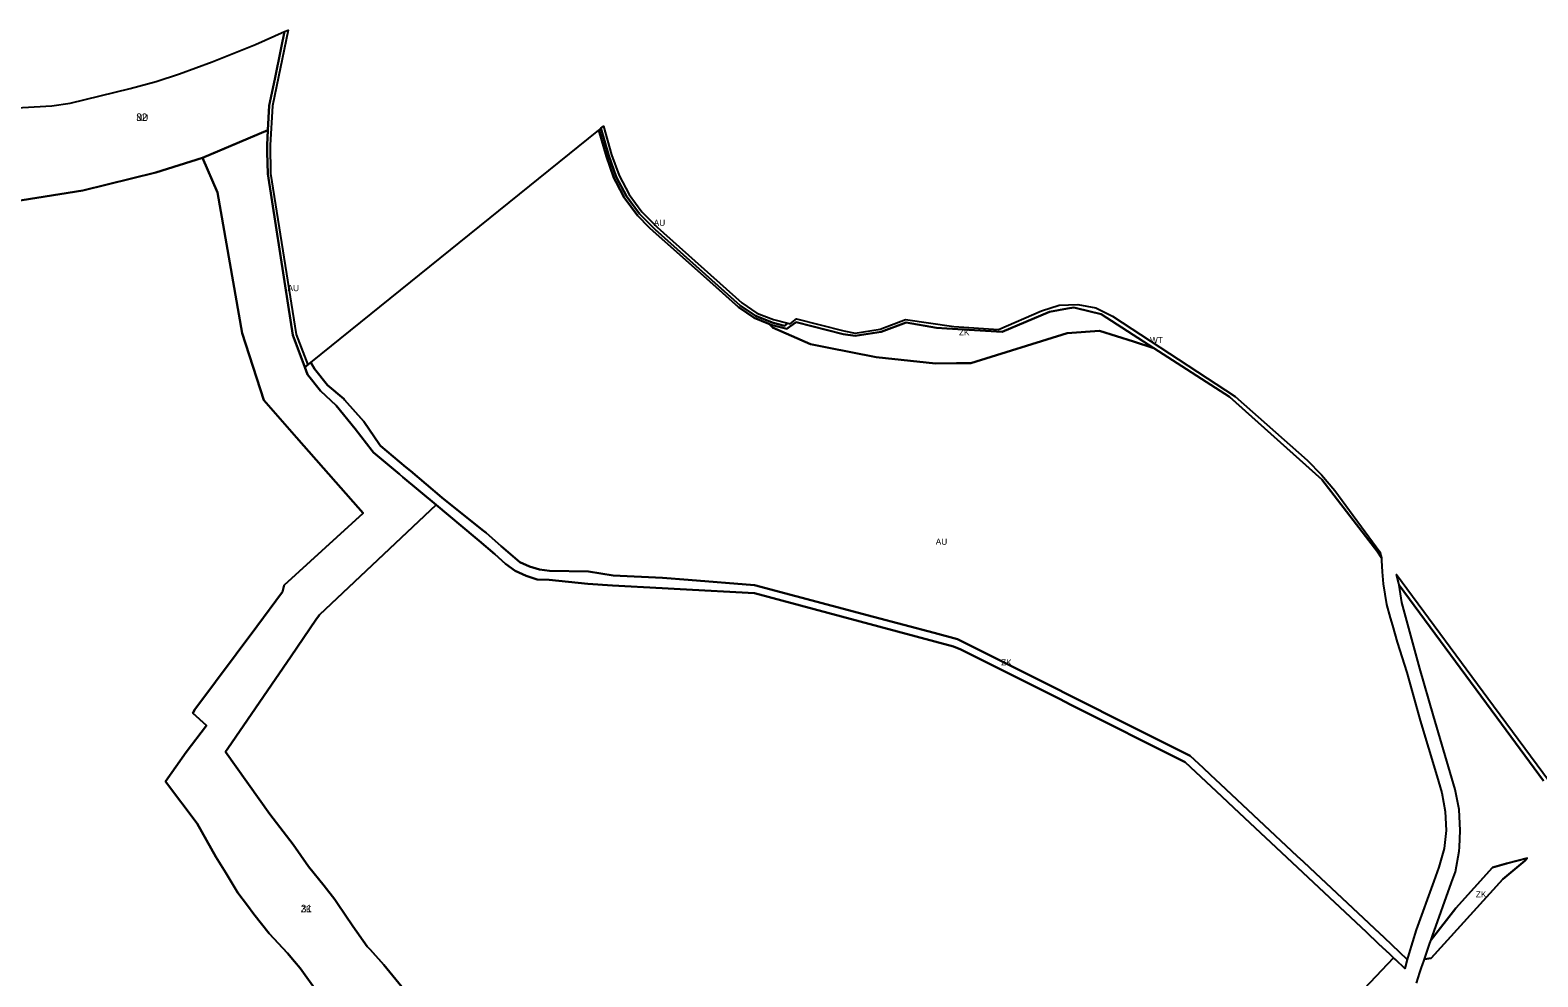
# Model space of a CAD drawing. Extents: x -541351 to -537540, y -1162694 to -1159725.
# Drawn here: x -539459 to -538243, y -1160701 to -1159939 of the extents above; entities that cross this region are included whole.
import ezdxf

# ---------------------------------------------------------------- set-up
doc = ezdxf.new("R2010")
doc.units = 0
for name, color, linetype in [('90640013', 7, 'Continuous'), ('90710013', 7, 'Continuous'), ('90710023', 7, 'Continuous'), ('90730023', 7, 'Continuous'), ('90750013', 7, 'Continuous'), ('ID_navrh', 7, 'Continuous')]:
    doc.layers.add(name, color=color, linetype=linetype)

msp = doc.modelspace()

# ---------------------------------------------------------------- linework, layer by layer
at = {"layer": '90640013'}
msp.add_lwpolyline([(-538370.49, -1160358.94), (-538369.3, -1160363.86), (-538372.22, -1160359.25), (-538417.44, -1160300.69), (-538491.9, -1160234.05), (-538552.96, -1160194.72), (-538595.44, -1160167.36), (-538615.23, -1160162.49), (-538617.34, -1160161.97), (-538622.38, -1160162.91), (-538637.02, -1160165.65), (-538675.11, -1160181.63), (-538719.64, -1160179.01), (-538728.21, -1160178.51), (-538752.52, -1160174.23), (-538772.82, -1160181.69), (-538793.6, -1160184.93), (-538803.32, -1160183.46), (-538841.31, -1160173.9), (-538846.77, -1160177.7), (-538848.8, -1160179.32), (-538860.75, -1160176.21), (-538863.2, -1160175.22), (-538875.02, -1160170.41), (-538887.73, -1160161.8), (-538910.96, -1160141.13), (-538935.46, -1160119.47), (-538956.49, -1160100.62), (-538959.62, -1160097.82), (-538969.1, -1160087.93), (-538979.86, -1160073.37), (-538986.39, -1160060.99), (-538988.26, -1160057.45), (-538994.28, -1160040.49), (-539000.5, -1160019.14), (-538998.75, -1160017.67), (-538992.36, -1160039.83), (-538986.31, -1160056.85), (-538978.16, -1160072.22), (-538967.47, -1160086.7), (-538955.06, -1160099.12), (-538886.36, -1160160.36), (-538874.16, -1160168.65), (-538859.9, -1160174.32), (-538850.66, -1160176.7), (-538848.02, -1160174.62), (-538846.13, -1160175.14), (-538840.94, -1160171.26), (-538822.03, -1160176.13), (-538802.78, -1160180.96), (-538793.68, -1160182.67), (-538773.4, -1160179.43), (-538753.21, -1160171.71), (-538714.09, -1160177.36), (-538678.11, -1160179.77), (-538643.45, -1160164.73), (-538629.14, -1160160.19), (-538614.23, -1160159.55), (-538599.49, -1160162.42), (-538586.2, -1160168.91), (-538487.18, -1160233.62), (-538429.21, -1160285.01), (-538417.52, -1160296.82), (-538407, -1160309.44)], close=True, dxfattribs=at)
msp.add_lwpolyline([(-538238.54, -1160543.48), (-538272.58, -1160497.42), (-538355.12, -1160385.74), (-538355.32, -1160384.48), (-538357.11, -1160377.08), (-538279, -1160482.96), (-538213.92, -1160570.92)], dxfattribs=at)
at = {"layer": '90710013'}
for points in [[(-538617.34, -1160161.97), (-538615.23, -1160162.49), (-538595.44, -1160167.36), (-538552.96, -1160194.72), (-538569.34, -1160189.52), (-538596.72, -1160180.83), (-538622.65, -1160182.66), (-538700.4, -1160206.89), (-538711.86, -1160206.99), (-538728.99, -1160207.15), (-538776.87, -1160201.94), (-538816.21, -1160194.19), (-538829.68, -1160191.54), (-538860.3, -1160178.14), (-538863.2, -1160175.22), (-538860.75, -1160176.21), (-538848.8, -1160179.32), (-538846.77, -1160177.7), (-538841.31, -1160173.9), (-538803.32, -1160183.46), (-538793.6, -1160184.93), (-538772.82, -1160181.69), (-538752.52, -1160174.23), (-538728.21, -1160178.51), (-538719.64, -1160179.01), (-538675.11, -1160181.63), (-538637.02, -1160165.65), (-538622.38, -1160162.91)], [(-539229.72, -1160211.49), (-539219.19, -1160224.51), (-539206.08, -1160235.73), (-539205.45, -1160236.44), (-539189.95, -1160253.97), (-539177.24, -1160272.53), (-539176.56, -1160273.52), (-539155.94, -1160290.64), (-539152.16, -1160293.52), (-539127.06, -1160315.25), (-539094.38, -1160341.15), (-539091.17, -1160343.7), (-539079.28, -1160354.4), (-539064.1, -1160367.35), (-539056.23, -1160370.78), (-539048.36, -1160373.06), (-539040.21, -1160374.33), (-539008.72, -1160374.73), (-538988.93, -1160377.95), (-538948.98, -1160379.96), (-538928.34, -1160381.56), (-538874.8, -1160385.7), (-538778.94, -1160411.23), (-538730.03, -1160424.25), (-538711.16, -1160429.21), (-538647.61, -1160461.1), (-538642.87, -1160463.48), (-538579.55, -1160495.26), (-538562.84, -1160503.65), (-538554.08, -1160508.04), (-538523.56, -1160523.26), (-538513.09, -1160533.06), (-538507.03, -1160538.72), (-538499.15, -1160546.09), (-538437.13, -1160604.1), (-538432.16, -1160608.74), (-538422.47, -1160617.85), (-538379.46, -1160658.24), (-538374.69, -1160662.73), (-538367.2, -1160669.76), (-538348.53, -1160687.31), (-538350.5, -1160694.55), (-538357.79, -1160687.71), (-538359.69, -1160685.93), (-538362.6, -1160683.19), (-538371.67, -1160674.68), (-538381.47, -1160665.47), (-538488.42, -1160565.07), (-538498.07, -1160556.01), (-538527.59, -1160528.3), (-538619.68, -1160482.15), (-538629.02, -1160477.47), (-538708.61, -1160437.58), (-538714.39, -1160435.25), (-538804.8, -1160411.03), (-538815.82, -1160408.08), (-538874.79, -1160392.29), (-538934.85, -1160388.95), (-538949.42, -1160388.13), (-538989.36, -1160385.91), (-539009.33, -1160384.8), (-539040.55, -1160381.4), (-539050.13, -1160381.07), (-539058.9, -1160378.15), (-539067.91, -1160374.21), (-539075.66, -1160368.49), (-539084.19, -1160360.78), (-539097, -1160350.07), (-539100.19, -1160347.41), (-539131.64, -1160321.1), (-539158.37, -1160298.74), (-539161.25, -1160296.33), (-539182.23, -1160278.79), (-539183.21, -1160277.53), (-539196.85, -1160259.88), (-539212.25, -1160241.09), (-539224.77, -1160229.29), (-539235.42, -1160215.92), (-539237.55, -1160210.2), (-539235.05, -1160208.26), (-539232.65, -1160206.32)], [(-538251.69, -1160605.72), (-538253.7, -1160607.81), (-538271.4, -1160622.7), (-538329.33, -1160686.32), (-538334.69, -1160687.17), (-538330.23, -1160674.25), (-538329.28, -1160671.49), (-538309.39, -1160646.13), (-538279.85, -1160613.21), (-538268.39, -1160610.16)]]:
    msp.add_lwpolyline(points, close=True, dxfattribs=at)
at = {"layer": '90710023'}
msp.add_lwpolyline([(-539226.94, -1160714.26), (-539241.32, -1160694.3), (-539245.9, -1160688.87), (-539251.45, -1160682.3), (-539266.3, -1160666.41), (-539278.49, -1160650.74), (-539283.75, -1160643.82), (-539291.4, -1160633.74), (-539301.24, -1160617.66), (-539309.15, -1160604.74), (-539324.22, -1160577.77), (-539349.79, -1160543.92), (-539333.25, -1160520.38), (-539316.91, -1160498.74), (-539327.896, -1160488.77), (-539326.21, -1160485.94), (-539276.18, -1160418.95), (-539255.5, -1160391.26), (-539254.28, -1160385.71), (-539190.466, -1160327.844), (-539212.408, -1160302.893), (-539244.187, -1160266.755), (-539270.58, -1160236.742), (-539288.051, -1160182.795), (-539307.802, -1160069.322), (-539320.05, -1160041.46), (-539307.802, -1160036.303), (-539267.32, -1160019.26), (-539267.84, -1160031.16), (-539267.74, -1160037), (-539267.44, -1160054.36), (-539250.94, -1160160.23), (-539247.17, -1160184.44), (-539237.55, -1160210.2), (-539235.42, -1160215.92), (-539224.77, -1160229.29), (-539212.25, -1160241.09), (-539196.85, -1160259.88), (-539183.21, -1160277.53), (-539182.23, -1160278.79), (-539161.25, -1160296.33), (-539158.37, -1160298.74), (-539131.64, -1160321.1), (-539225.75, -1160409.65), (-539228.529, -1160413.704), (-539248.605, -1160442.984), (-539299.619, -1160517.39), (-539301.519, -1160520.161), (-539265.58, -1160570.18), (-539246.94, -1160594.62), (-539234.4, -1160612.53), (-539221.81, -1160628.07), (-539213.34, -1160639.09), (-539211.27, -1160642.16), (-539198.78, -1160660.64), (-539187.18, -1160676.86), (-539184.91, -1160679.39), (-539173.73, -1160691.8), (-539159.22, -1160709.51)], dxfattribs=at)
at = {"layer": '90730023'}
msp.add_lwpolyline([(-539504.15, -1160057.74), (-539499.27, -1160048.44), (-539494.95, -1160040.2), (-539486.82, -1160024.7), (-539482.04, -1160015.57), (-539474.65, -1160001.49), (-539441.58, -1159999.6), (-539426.66, -1159997.49), (-539378.27, -1159985.56), (-539357.29, -1159979.97), (-539338.63, -1159973.85), (-539312.29, -1159964.05), (-539277.38, -1159950.13), (-539253.79, -1159939.77), (-539256.52, -1159952.89), (-539261.76, -1159978), (-539266.2, -1159999.29), (-539267.32, -1160019.26), (-539320.05, -1160041.46), (-539357.51, -1160053.36), (-539416.53, -1160067.73), (-539516.34, -1160083.61), (-539513.23, -1160077.01)], close=True, dxfattribs=at)
at = {"layer": '90750013'}
for points in [[(-539263.64, -1159999.6), (-539265.33, -1160031.19), (-539265.24, -1160054.12), (-539244.59, -1160183.77), (-539235.05, -1160208.26), (-539237.55, -1160210.2), (-539247.17, -1160184.44), (-539250.94, -1160160.23), (-539267.44, -1160054.36), (-539267.74, -1160037), (-539267.84, -1160031.16), (-539267.32, -1160019.26), (-539266.2, -1159999.29), (-539261.76, -1159978), (-539256.52, -1159952.89), (-539253.79, -1159939.77), (-539251.01, -1159938.59)], [(-538417.44, -1160300.69), (-538372.22, -1160359.25), (-538369.3, -1160363.86), (-538369.19, -1160365.99), (-538368.74, -1160375.12), (-538367.88, -1160384.77), (-538365.12, -1160401.34), (-538362.23, -1160412.05), (-538360.43, -1160418.26), (-538356.56, -1160431.65), (-538348.78, -1160456.25), (-538337.94, -1160494.81), (-538324.7, -1160539.29), (-538320.65, -1160553.21), (-538317.93, -1160568.07), (-538317.03, -1160583.49), (-538318.62, -1160597.9), (-538323.05, -1160612.86), (-538327.17, -1160624.4), (-538341.19, -1160663.56), (-538347.11, -1160682.71), (-538348.53, -1160687.31), (-538367.2, -1160669.76), (-538374.69, -1160662.73), (-538379.46, -1160658.24), (-538422.47, -1160617.85), (-538432.16, -1160608.74), (-538437.13, -1160604.1), (-538499.15, -1160546.09), (-538507.03, -1160538.72), (-538513.09, -1160533.06), (-538523.56, -1160523.26), (-538554.08, -1160508.04), (-538562.84, -1160503.65), (-538579.55, -1160495.26), (-538642.87, -1160463.48), (-538647.61, -1160461.1), (-538711.16, -1160429.21), (-538730.03, -1160424.25), (-538778.94, -1160411.23), (-538874.8, -1160385.7), (-538928.34, -1160381.56), (-538948.98, -1160379.96), (-538988.93, -1160377.95), (-539008.72, -1160374.73), (-539040.21, -1160374.33), (-539048.36, -1160373.06), (-539056.23, -1160370.78), (-539064.1, -1160367.35), (-539079.28, -1160354.4), (-539091.17, -1160343.7), (-539094.38, -1160341.15), (-539127.06, -1160315.25), (-539152.16, -1160293.52), (-539155.94, -1160290.64), (-539176.56, -1160273.52), (-539177.24, -1160272.53), (-539189.95, -1160253.97), (-539205.45, -1160236.44), (-539206.08, -1160235.73), (-539219.19, -1160224.51), (-539229.72, -1160211.49), (-539232.65, -1160206.32), (-539000.5, -1160019.14), (-538994.28, -1160040.49), (-538988.26, -1160057.45), (-538986.39, -1160060.99), (-538979.86, -1160073.37), (-538969.1, -1160087.93), (-538959.62, -1160097.82), (-538956.49, -1160100.62), (-538935.46, -1160119.47), (-538910.96, -1160141.13), (-538887.73, -1160161.8), (-538875.02, -1160170.41), (-538863.2, -1160175.22), (-538860.3, -1160178.14), (-538829.68, -1160191.54), (-538816.21, -1160194.19), (-538776.87, -1160201.94), (-538728.99, -1160207.15), (-538711.86, -1160206.99), (-538700.4, -1160206.89), (-538622.65, -1160182.66), (-538596.72, -1160180.83), (-538569.34, -1160189.52), (-538552.96, -1160194.72), (-538491.9, -1160234.05)], [(-538990.06, -1160039.15), (-538984.11, -1160055.68), (-538975.92, -1160070.9), (-538965.59, -1160084.97), (-538953.46, -1160097.34), (-538885.01, -1160158.23), (-538872.92, -1160166.48), (-538859.62, -1160171.76), (-538848.02, -1160174.62), (-538850.66, -1160176.7), (-538859.9, -1160174.32), (-538874.16, -1160168.65), (-538886.36, -1160160.36), (-538955.06, -1160099.12), (-538967.47, -1160086.7), (-538978.16, -1160072.22), (-538986.31, -1160056.85), (-538992.36, -1160039.83), (-538998.75, -1160017.67), (-538996.64, -1160015.93)]]:
    msp.add_lwpolyline(points, close=True, dxfattribs=at)
for points in [[(-539516.34, -1160083.61), (-539416.53, -1160067.73), (-539357.51, -1160053.36), (-539320.05, -1160041.46), (-539307.802, -1160069.322), (-539288.051, -1160182.795), (-539270.58, -1160236.742), (-539244.187, -1160266.755), (-539212.408, -1160302.893), (-539190.466, -1160327.844), (-539254.28, -1160385.71), (-539255.5, -1160391.26), (-539276.18, -1160418.95), (-539326.21, -1160485.94), (-539327.896, -1160488.77), (-539316.91, -1160498.74), (-539333.25, -1160520.38), (-539349.79, -1160543.92), (-539324.22, -1160577.77), (-539309.15, -1160604.74), (-539301.24, -1160617.66), (-539291.4, -1160633.74), (-539283.75, -1160643.82), (-539278.49, -1160650.74), (-539266.3, -1160666.41), (-539251.45, -1160682.3), (-539245.9, -1160688.87), (-539241.32, -1160694.3), (-539226.94, -1160714.26)], [(-539159.22, -1160709.51), (-539173.73, -1160691.8), (-539184.91, -1160679.39), (-539187.18, -1160676.86), (-539198.78, -1160660.64), (-539211.27, -1160642.16), (-539213.34, -1160639.09), (-539221.81, -1160628.07), (-539234.4, -1160612.53), (-539246.94, -1160594.62), (-539265.58, -1160570.18), (-539301.519, -1160520.161), (-539299.619, -1160517.39), (-539248.605, -1160442.984), (-539228.529, -1160413.704), (-539225.75, -1160409.65), (-539131.64, -1160321.1), (-539100.19, -1160347.41), (-539097, -1160350.07), (-539084.19, -1160360.78), (-539075.66, -1160368.49), (-539067.91, -1160374.21), (-539058.9, -1160378.15), (-539050.13, -1160381.07), (-539040.55, -1160381.4), (-539009.33, -1160384.8), (-538989.36, -1160385.91), (-538949.42, -1160388.13), (-538934.85, -1160388.95), (-538874.79, -1160392.29), (-538815.82, -1160408.08), (-538804.8, -1160411.03), (-538714.39, -1160435.25), (-538708.61, -1160437.58), (-538629.02, -1160477.47), (-538619.68, -1160482.15), (-538527.59, -1160528.3), (-538498.07, -1160556.01), (-538488.42, -1160565.07), (-538381.47, -1160665.47), (-538371.67, -1160674.68), (-538362.6, -1160683.19), (-538359.69, -1160685.93), (-538397.64, -1160726.21)], [(-538341.15, -1160706.33), (-538338.41, -1160697.91), (-538336.76, -1160693.14), (-538336.54, -1160692.52), (-538334.69, -1160687.17), (-538329.33, -1160686.32), (-538271.4, -1160622.7), (-538253.7, -1160607.81), (-538251.69, -1160605.72), (-538268.39, -1160610.16), (-538279.85, -1160613.21), (-538309.39, -1160646.13), (-538329.28, -1160671.49), (-538328.18, -1160668.31), (-538312.77, -1160625.25), (-538309.68, -1160616.62), (-538306.6, -1160600.01), (-538306.26, -1160596.82), (-538305.82, -1160583.33), (-538306.54, -1160566.65), (-538309.86, -1160550.28), (-538315.19, -1160532.1), (-538327.23, -1160491.04), (-538338.41, -1160452.93), (-538348.84, -1160414.57), (-538352.88, -1160399.7), (-538355.12, -1160385.74), (-538272.58, -1160497.42), (-538238.54, -1160543.48)]]:
    msp.add_lwpolyline(points, dxfattribs=at)

# ---------------------------------------------------------------- texts
at = {"layer": '90640013'}
msp.add_text('WT', height=5, rotation=360, dxfattribs=at).set_placement((-538555.929, -1160190.765))
at = {"layer": '90710013'}
for p in [(-538709.987, -1160184.56), (-538675.912, -1160450.435), (-538293.19, -1160637.353)]:
    msp.add_text('ZK', height=5, rotation=0, dxfattribs=at).set_placement(p)
at = {"layer": '90710023'}
msp.add_text('ZK', height=5, rotation=0, dxfattribs=at).set_placement((-539240.715, -1160649.325))
at = {"layer": '90730023'}
msp.add_text('NU', height=5, rotation=360, dxfattribs=at).set_placement((-539373.449, -1160011.69))
at = {"layer": '90750013'}
for rotation, p in [(360, (-538956.164, -1160096.315)), (0, (-539251.445, -1160148.86)), (360, (-538728.729, -1160353.225))]:
    msp.add_text('AU', height=5, rotation=rotation, dxfattribs=at).set_placement(p)
at = {"layer": 'ID_navrh'}
for s, rotation, p in [('32', 360, (-539373.449, -1160011.69)), ('31', 0, (-539240.715, -1160649.325))]:
    msp.add_text(s, height=6, rotation=rotation, dxfattribs=at).set_placement(p)

doc.saveas('drawing.dxf')
